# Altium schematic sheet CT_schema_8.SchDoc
size 287 x 160 mm
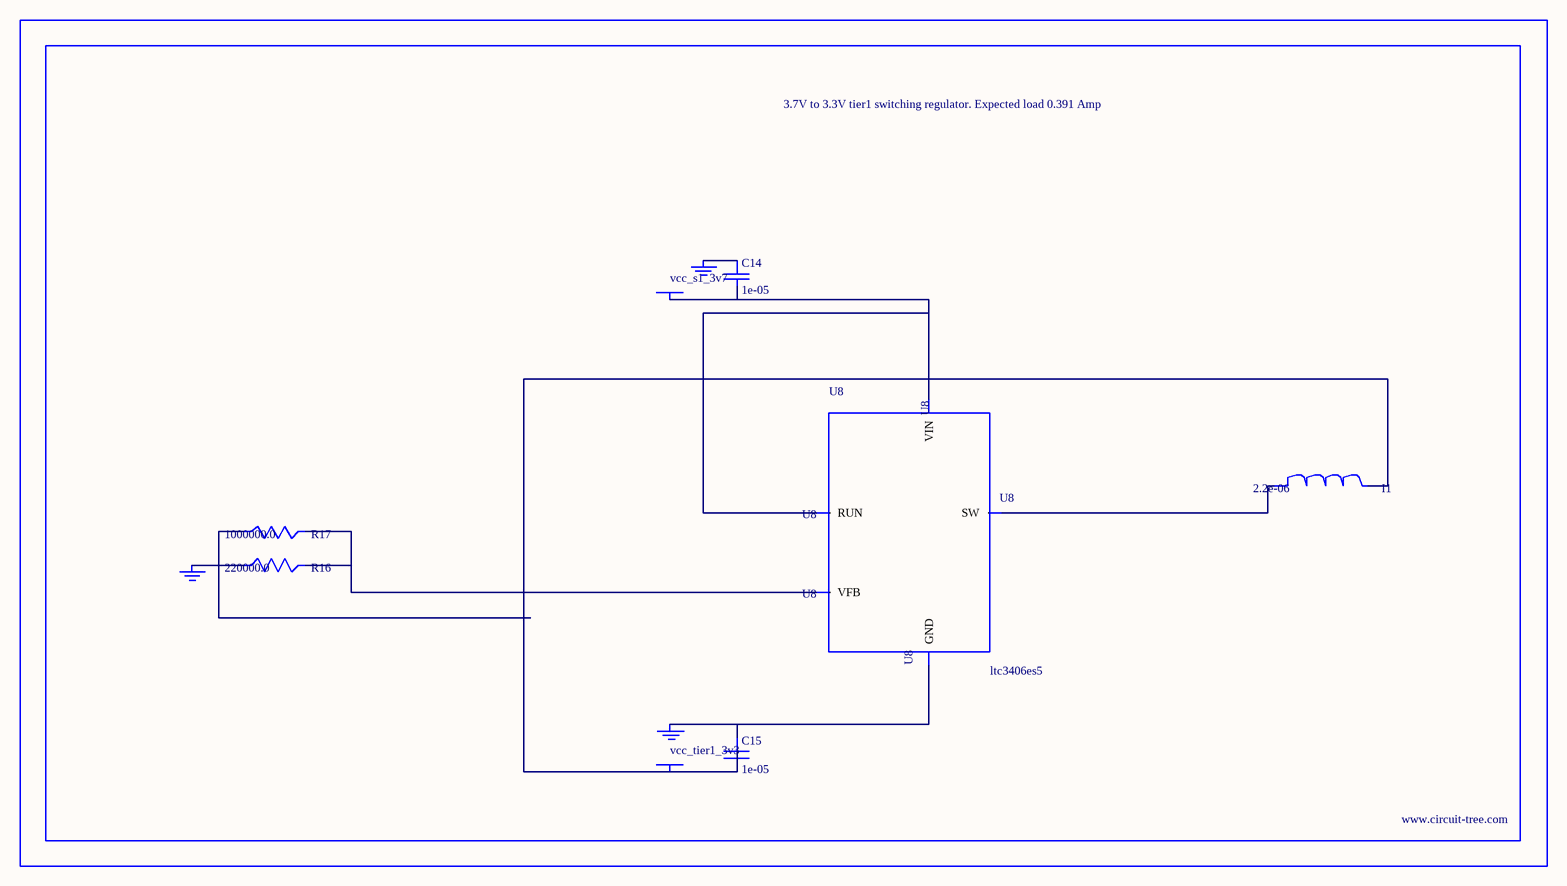
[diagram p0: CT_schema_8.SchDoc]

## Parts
BORDER7  (no value)
C14  1e-05  [C0805]
C15  1e-05  [C0805]
GND_INSTANCE_7_0  (no value)
GND_INSTANCE_7_1  (no value)
GND_INSTANCE_7_2  (no value)
I1  2.2e-06  [L0805]
POWER_INSTANCE_7_0  vcc_tier1_3v3
POWER_INSTANCE_7_1  vcc_s1_3v7
R16  220000.0  [R0603]
R17  1000000.0  [R0603]
U8  ltc3406es5  [TSOT-23-5]

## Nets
NetC14_1: C14.1 GND_INSTANCE_7_1.0(GND)
NetC14_2: C14.2 POWER_INSTANCE_7_1.0(PWR) U8.1(RUN) U8.4(VIN)
NetC15_1: C15.1 GND_INSTANCE_7_0.0(GND) U8.2(GND)
NetC15_2: C15.2 I1.2 POWER_INSTANCE_7_0.0(PWR) R17.1
NetGND_INSTANCE_7_2_0: GND_INSTANCE_7_2.0(GND) R16.1
NetI1_1: I1.1 U8.3(SW)
NetR16_2: R16.2 R17.2 U8.5(VFB)

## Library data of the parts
BORDER7 = BORDER_PAGE7
C14 C15 = C0805C106K8RACTU
GND_INSTANCE_7_0-GND_INSTANCE_7_2 = GND
I1 = L0805C2R2MDWIT
POWER_INSTANCE_7_0 POWER_INSTANCE_7_1 = PWR
R16 = RC0603JR-07220KL
R17 = RC0603JR-071ML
